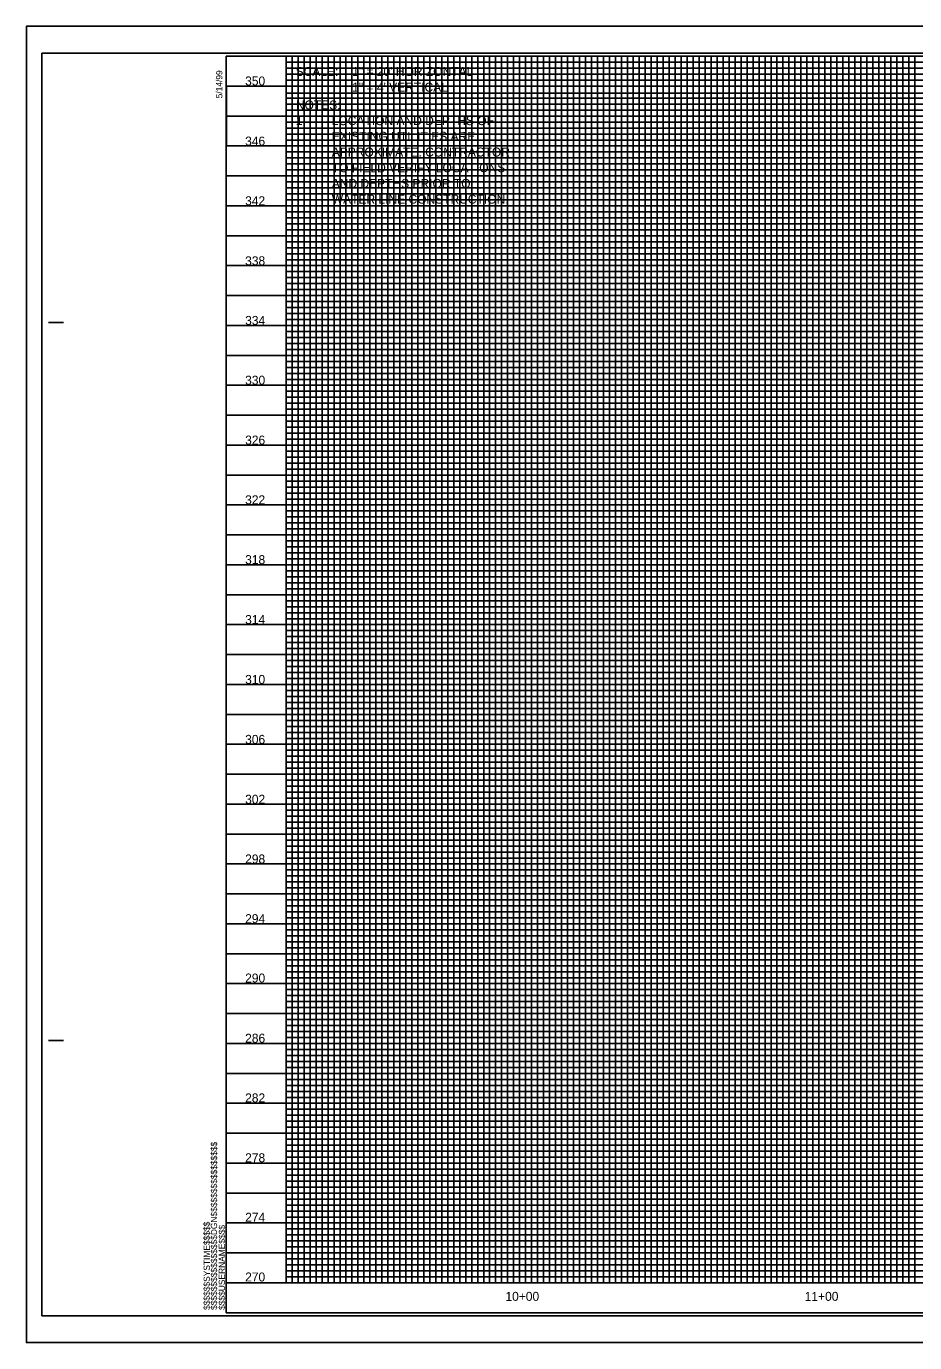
# Model space of a CAD drawing. Extents: x 3814791 to 3815465, y 1224203 to 1224643.
# Drawn here: x 3814791.3 to 3815088.1, y 1224203.2 to 1224643.2 of the extents above; entities that cross this region are included whole.
import ezdxf

# ---------------------------------------------------------------- set-up
doc = ezdxf.new("R2010")
doc.units = 0
for name, color, linetype in [('Exist Roads EOP', 7, 'Continuous'), ('General Text and Text Box and Leader Line', 7, 'Continuous'), ('Pattern 49', 7, 'Continuous'), ('Scratch_Level_1', 7, 'Continuous'), ('W 45 B (St) CELL', 7, 'Continuous'), ('Water Pump Station (St) CELL', 7, 'Continuous')]:
    doc.layers.add(name, color=color, linetype=linetype)

msp = doc.modelspace()

# ---------------------------------------------------------------- linework, layer by layer
at = {"layer": 'Exist Roads EOP'}
for p, q in [((3814878.11, 1224633.21), (3815378.11, 1224633.21)), ((3815438.11, 1224561.21), (3814878.11, 1224561.21)), ((3814878.11, 1224561.21), (3814878.11, 1224559.21)), ((3814878.11, 1224559.21), (3815438.11, 1224559.21)), ((3815438.11, 1224551.21), (3814878.11, 1224551.21)), ((3814798.71, 1224544.21), (3814803.71, 1224544.21)), ((3814798.71, 1224304.21), (3814803.71, 1224304.21)), ((3815458.11, 1224223.21), (3814858.11, 1224223.21)), ((3814878.11, 1224223.21), (3815438.11, 1224223.21)), ((3814858.11, 1224213.21), (3814858.11, 1224213.21)), ((3814858.11, 1224213.21), (3814858.11, 1224213.21)), ((3814858.11, 1224213.21), (3814858.11, 1224213.21)), ((3814858.11, 1224213.21), (3814858.11, 1224213.21)), ((3814858.11, 1224213.21), (3814858.11, 1224213.21)), ((3814858.11, 1224213.21), (3814858.11, 1224213.21))]:
    msp.add_line(p, q, dxfattribs=at)
for points in [[(3815458.11, 1224633.21), (3814858.11, 1224633.21), (3814858.11, 1224213.21), (3815458.11, 1224213.21)], [(3814878.11, 1224633.21), (3814878.11, 1224223.21), (3815438.11, 1224223.21), (3815438.11, 1224578.19), (3815378.11, 1224578.19), (3815378.11, 1224633.21)]]:
    msp.add_lwpolyline(points, close=True, dxfattribs=at)
for points in [[(3814878.11, 1224633.21), (3814878.11, 1224223.21), (3814898.11, 1224223.21), (3814898.11, 1224633.21), (3814918.11, 1224633.21), (3814918.11, 1224223.21), (3814938.11, 1224223.21), (3814938.11, 1224633.21), (3814958.11, 1224633.21), (3814958.11, 1224223.21), (3814978.11, 1224223.21), (3814978.11, 1224633.21), (3814998.11, 1224633.21), (3814998.11, 1224223.21), (3815018.11, 1224223.21), (3815018.11, 1224633.21), (3815038.11, 1224633.21), (3815038.11, 1224223.21), (3815058.11, 1224223.21), (3815058.11, 1224633.21), (3815078.11, 1224633.21), (3815078.11, 1224223.21), (3815098.11, 1224223.21)], [(3814878.11, 1224633.21), (3814880.11, 1224633.21), (3814880.11, 1224223.21), (3814882.11, 1224223.21), (3814882.11, 1224633.21), (3814884.11, 1224633.21), (3814884.11, 1224223.21), (3814886.11, 1224223.21), (3814886.11, 1224633.21), (3814890.11, 1224633.21), (3814890.11, 1224223.21), (3814892.11, 1224223.21), (3814892.11, 1224633.21), (3814894.11, 1224633.21), (3814894.11, 1224223.21), (3814896.11, 1224223.21), (3814896.11, 1224633.21), (3814900.11, 1224633.21), (3814900.11, 1224223.21), (3814902.11, 1224223.21), (3814902.11, 1224633.21), (3814904.11, 1224633.21), (3814904.11, 1224223.21), (3814906.11, 1224223.21), (3814906.11, 1224633.21), (3814910.11, 1224633.21), (3814910.11, 1224223.21), (3814912.11, 1224223.21), (3814912.11, 1224633.21), (3814914.11, 1224633.21), (3814914.11, 1224223.21), (3814916.11, 1224223.21), (3814916.11, 1224633.21), (3814920.11, 1224633.21), (3814920.11, 1224223.21), (3814922.11, 1224223.21), (3814922.11, 1224633.21), (3814924.11, 1224633.21), (3814924.11, 1224223.21), (3814926.11, 1224223.21), (3814926.11, 1224633.21), (3814930.11, 1224633.21), (3814930.11, 1224223.21), (3814932.11, 1224223.21), (3814932.11, 1224633.21), (3814934.11, 1224633.21), (3814934.11, 1224223.21), (3814936.11, 1224223.21), (3814936.11, 1224633.21), (3814940.11, 1224633.21), (3814940.11, 1224223.21), (3814942.11, 1224223.21), (3814942.11, 1224633.21), (3814944.11, 1224633.21), (3814944.11, 1224223.21)], [(3815378.09, 1224631.21), (3814878.11, 1224631.21), (3814878.11, 1224629.21), (3815378.09, 1224629.21)], [(3814888.11, 1224223.21), (3814888.11, 1224633.21), (3814908.11, 1224633.21), (3814908.11, 1224223.21), (3814928.11, 1224223.21), (3814928.11, 1224633.21), (3814948.11, 1224633.21), (3814948.11, 1224223.21), (3814968.11, 1224223.21), (3814968.11, 1224633.21), (3814988.11, 1224633.21), (3814988.11, 1224223.21), (3815008.11, 1224223.21), (3815008.11, 1224633.21), (3815028.11, 1224633.21), (3815028.11, 1224223.21), (3815048.11, 1224223.21), (3815048.11, 1224633.21), (3815068.11, 1224633.21), (3815068.11, 1224223.21), (3815088.11, 1224223.21), (3815088.11, 1224633.21)], [(3814944.11, 1224223.21), (3814946.11, 1224223.21), (3814946.11, 1224633.21), (3814950.11, 1224633.21), (3814950.11, 1224223.21), (3814952.11, 1224223.21), (3814952.11, 1224633.21), (3814954.11, 1224633.21), (3814954.11, 1224223.21), (3814956.11, 1224223.21), (3814956.11, 1224633.21), (3814960.11, 1224633.21), (3814960.11, 1224223.21), (3814962.11, 1224223.21), (3814962.11, 1224633.21), (3814962.11, 1224633.21), (3814964.11, 1224633.21), (3814964.11, 1224223.21), (3814966.11, 1224223.21), (3814966.11, 1224633.21), (3814970.11, 1224633.21), (3814970.11, 1224223.21), (3814972.11, 1224223.21), (3814972.11, 1224633.21), (3814974.11, 1224633.21), (3814974.11, 1224223.21), (3814976.11, 1224223.21), (3814976.11, 1224633.21), (3814980.11, 1224633.21), (3814980.11, 1224223.21), (3814982.11, 1224223.21), (3814982.11, 1224633.21), (3814984.11, 1224633.21), (3814984.11, 1224223.21), (3814986.11, 1224223.21), (3814986.11, 1224633.21), (3814990.11, 1224633.21), (3814990.11, 1224223.21), (3814992.11, 1224223.21), (3814992.11, 1224633.21), (3814994.11, 1224633.21), (3814994.11, 1224223.21), (3814996.11, 1224223.21), (3814996.11, 1224633.21), (3815000.11, 1224633.21), (3815000.11, 1224223.21), (3815002.11, 1224223.21), (3815002.11, 1224633.21), (3815004.11, 1224633.21), (3815004.11, 1224223.21), (3815006.11, 1224223.21), (3815006.11, 1224633.21), (3815010.11, 1224633.21), (3815010.11, 1224223.21), (3815016.11, 1224223.21), (3815016.11, 1224633.21), (3815020.11, 1224633.21), (3815020.11, 1224223.21), (3815022.11, 1224223.21), (3815022.11, 1224633.21), (3815024.11, 1224633.21), (3815024.11, 1224223.21), (3815026.11, 1224223.21), (3815026.11, 1224633.21), (3815030.11, 1224633.21), (3815030.11, 1224223.21), (3815032.11, 1224223.21), (3815032.11, 1224633.21), (3815034.11, 1224633.21), (3815034.11, 1224223.21), (3815036.11, 1224223.21), (3815036.11, 1224633.21), (3815040.11, 1224633.21), (3815040.11, 1224223.21), (3815042.11, 1224223.21), (3815042.11, 1224633.21), (3815044.11, 1224633.21), (3815044.11, 1224223.21), (3815046.11, 1224223.21), (3815046.11, 1224633.21), (3815050.11, 1224633.21), (3815050.11, 1224223.21), (3815052.11, 1224223.21), (3815052.11, 1224633.21), (3815054.11, 1224633.21), (3815054.11, 1224223.21), (3815056.11, 1224223.21), (3815056.11, 1224633.21), (3815060.11, 1224633.21), (3815060.11, 1224223.21), (3815062.11, 1224223.21), (3815062.11, 1224633.21), (3815064.11, 1224633.21), (3815064.11, 1224223.21), (3815066.11, 1224223.21), (3815066.11, 1224633.21), (3815070.11, 1224633.21), (3815070.11, 1224223.21)], [(3815012.11, 1224633.21), (3815012.11, 1224223.21), (3815014.11, 1224223.21), (3815014.11, 1224633.21)], [(3815012.11, 1224632.97), (3815012.11, 1224223.21), (3815014.11, 1224223.21), (3815014.11, 1224632.97)], [(3815072.11, 1224633.21), (3815072.11, 1224223.21), (3815074.11, 1224223.21), (3815074.11, 1224633.21), (3815076.11, 1224633.21), (3815076.11, 1224223.21), (3815080.11, 1224223.21), (3815080.11, 1224633.21), (3815082.11, 1224633.21), (3815082.11, 1224223.21), (3815084.11, 1224223.21), (3815084.11, 1224633.21), (3815086.11, 1224633.21), (3815086.11, 1224223.21)], [(3815378.09, 1224627.21), (3814878.11, 1224627.21), (3814878.11, 1224625.21), (3815378.09, 1224625.21)], [(3815378.09, 1224603.21), (3814858.15, 1224603.21), (3814858.15, 1224623.19), (3815378.09, 1224623.19)], [(3815378.09, 1224620.91), (3814878.11, 1224620.91), (3814878.11, 1224619.21), (3815378.09, 1224619.21)], [(3815378.09, 1224617.21), (3814878.11, 1224617.21), (3814878.11, 1224615.21), (3815378.09, 1224615.21)], [(3814858.11, 1224613.21), (3815378.09, 1224613.21)], [(3815378.09, 1224611.21), (3814878.11, 1224611.21), (3814878.11, 1224609.21), (3815378.09, 1224609.21)], [(3815378.11, 1224607.21), (3814878.11, 1224607.21), (3814878.11, 1224605.21), (3815378.09, 1224605.21)], [(3815378.09, 1224601.21), (3814878.11, 1224601.21), (3814878.11, 1224599.21), (3815378.09, 1224599.21)], [(3815378.09, 1224597.21), (3814878.11, 1224597.21), (3814878.11, 1224595.21), (3815378.09, 1224595.21)], [(3815378.09, 1224593.21), (3814858.11, 1224593.21), (3814858.11, 1224573.19), (3815458.11, 1224573.19)], [(3815378.09, 1224591.21), (3814878.11, 1224591.21), (3814878.11, 1224589.21), (3815378.09, 1224589.21)], [(3815378.09, 1224587.21), (3814878.11, 1224587.21), (3814878.11, 1224585.21), (3815378.09, 1224585.21)], [(3815458.11, 1224563.21), (3814858.11, 1224563.21), (3814858.11, 1224583.21), (3815378.09, 1224583.21)], [(3815378.09, 1224581.21), (3814878.11, 1224581.21), (3814878.11, 1224579.21), (3815378.09, 1224579.21)], [(3815438.11, 1224577.21), (3814878.11, 1224577.21), (3814878.11, 1224577.21), (3814878.11, 1224569.21), (3815458.11, 1224569.21)], [(3814878.11, 1224575.21), (3815378.11, 1224575.21)], [(3815438.11, 1224571.21), (3814878.11, 1224571.21)], [(3815438.11, 1224567.21), (3814878.11, 1224567.21), (3814878.11, 1224565.21), (3815438.11, 1224565.21)], [(3815438.11, 1224557.21), (3814878.11, 1224557.21), (3814878.11, 1224555.21), (3815438.11, 1224555.21)], [(3815458.11, 1224553.21), (3814858.11, 1224553.21), (3814858.11, 1224533.21), (3815458.11, 1224533.21)], [(3815438.11, 1224549.21), (3814878.11, 1224549.21), (3814878.11, 1224547.21), (3815438.11, 1224547.21)], [(3815458.11, 1224523.21), (3814858.11, 1224523.21), (3814858.11, 1224543.21), (3815458.11, 1224543.21)], [(3815438.11, 1224545.21), (3814878.11, 1224545.21)], [(3814878.11, 1224541.21), (3815438.11, 1224541.21)], [(3815438.11, 1224539.21), (3814878.11, 1224539.21), (3814878.11, 1224537.21), (3815438.11, 1224537.21)], [(3815438.11, 1224535.21), (3814878.11, 1224535.21), (3814878.11, 1224531.21), (3815438.11, 1224531.21)], [(3815438.11, 1224529.21), (3814878.11, 1224529.21), (3814878.11, 1224527.21), (3815438.11, 1224527.21)], [(3815438.11, 1224525.21), (3814878.11, 1224525.21), (3814878.11, 1224521.21), (3815438.11, 1224521.21)], [(3815438.11, 1224519.21), (3814878.11, 1224519.21), (3814878.11, 1224517.21), (3815438.11, 1224517.21)], [(3815458.11, 1224513.21), (3814858.11, 1224513.21), (3814858.11, 1224493.21), (3815458.11, 1224493.21)], [(3815438.11, 1224515.21), (3814878.11, 1224515.21), (3814878.11, 1224511.21), (3815438.11, 1224511.21)], [(3815438.11, 1224509.21), (3814878.11, 1224509.21), (3814878.11, 1224507.21), (3815438.11, 1224507.21)], [(3815458.11, 1224483.21), (3814858.11, 1224483.21), (3814858.11, 1224503.21), (3815458.11, 1224503.21)], [(3815438.11, 1224505.21), (3814878.11, 1224505.21), (3814878.11, 1224501.21), (3815438.11, 1224501.21)], [(3815438.11, 1224499.21), (3814878.11, 1224499.21), (3814878.11, 1224497.21), (3815438.11, 1224497.21)], [(3815438.11, 1224495.21), (3814878.11, 1224495.21), (3814878.11, 1224491.21), (3815438.11, 1224491.21)], [(3815438.11, 1224489.21), (3814878.11, 1224489.21), (3814878.11, 1224487.21), (3815438.11, 1224487.21)], [(3815438.11, 1224485.21), (3814878.11, 1224485.21), (3814878.11, 1224481.21), (3815438.11, 1224481.21)], [(3815438.11, 1224479.21), (3814878.11, 1224479.21), (3814878.11, 1224477.21), (3815438.11, 1224477.21)], [(3815458.11, 1224473.21), (3814858.11, 1224473.21), (3814858.11, 1224453.21), (3815458.11, 1224453.21)], [(3815438.11, 1224475.21), (3814878.11, 1224475.21), (3814878.11, 1224471.21), (3815438.11, 1224471.21)], [(3815438.11, 1224469.21), (3814878.11, 1224469.21), (3814878.11, 1224467.21), (3815438.11, 1224467.21)], [(3815458.11, 1224443.21), (3814858.11, 1224443.21), (3814858.11, 1224463.21), (3815458.11, 1224463.21)], [(3815438.11, 1224465.21), (3814878.11, 1224465.21), (3814878.11, 1224461.21), (3815438.11, 1224461.21)], [(3815438.11, 1224459.21), (3814878.11, 1224459.21), (3814878.11, 1224457.21), (3815438.11, 1224457.21)], [(3815438.11, 1224455.21), (3814878.11, 1224455.21), (3814878.11, 1224451.21), (3815438.11, 1224451.21)], [(3815438.11, 1224449.21), (3814878.11, 1224449.21), (3814878.11, 1224447.21), (3815438.11, 1224447.21)], [(3815438.11, 1224445.21), (3814878.11, 1224445.21), (3814878.11, 1224441.21), (3815438.11, 1224441.21)], [(3815438.11, 1224439.21), (3814878.11, 1224439.21), (3814878.11, 1224437.21), (3815438.11, 1224437.21)], [(3815458.11, 1224433.21), (3814858.11, 1224433.21), (3814858.11, 1224413.21), (3815458.11, 1224413.21)], [(3815438.11, 1224435.21), (3814878.11, 1224435.21), (3814878.11, 1224431.21), (3815438.11, 1224431.21)], [(3815438.11, 1224429.21), (3814878.11, 1224429.21), (3814878.11, 1224427.21), (3815438.11, 1224427.21)], [(3815458.11, 1224403.21), (3814858.11, 1224403.21), (3814858.11, 1224423.21), (3815458.11, 1224423.21)], [(3815438.11, 1224425.21), (3814878.11, 1224425.21)], [(3814878.11, 1224421.21), (3815438.11, 1224421.21)], [(3815438.11, 1224419.21), (3814878.11, 1224419.21), (3814878.11, 1224417.21), (3815438.11, 1224417.21)], [(3815438.11, 1224415.21), (3814878.11, 1224415.21), (3814878.11, 1224411.21), (3815438.11, 1224411.21)], [(3815438.11, 1224409.21), (3814878.11, 1224409.21), (3814878.11, 1224407.21), (3815438.11, 1224407.21)], [(3815438.11, 1224405.21), (3814878.11, 1224405.21), (3814878.11, 1224401.21), (3815438.11, 1224401.21)], [(3815438.11, 1224399.21), (3814878.11, 1224399.21), (3814878.11, 1224397.21), (3815438.11, 1224397.21)], [(3815458.11, 1224393.21), (3814858.11, 1224393.21), (3814858.11, 1224373.21), (3815458.11, 1224373.21)], [(3815438.11, 1224395.21), (3814878.11, 1224395.21), (3814878.11, 1224391.21), (3815438.11, 1224391.21)], [(3815438.11, 1224389.21), (3814878.11, 1224389.21), (3814878.11, 1224387.21), (3815438.11, 1224387.21)], [(3815438.11, 1224385.21), (3814878.11, 1224385.21), (3814878.11, 1224381.21), (3815438.11, 1224381.21)], [(3815458.11, 1224363.21), (3814858.11, 1224363.21), (3814858.11, 1224383.21), (3815458.11, 1224383.21)], [(3815438.11, 1224379.21), (3814878.11, 1224379.21), (3814878.11, 1224377.21), (3815438.11, 1224377.21)], [(3815438.11, 1224375.21), (3814878.11, 1224375.21), (3814878.11, 1224371.21), (3815438.11, 1224371.21)], [(3815438.11, 1224369.21), (3814878.11, 1224369.21), (3814878.11, 1224367.21), (3815438.11, 1224367.21)], [(3815438.11, 1224365.21), (3814878.11, 1224365.21), (3814878.11, 1224361.21), (3815438.11, 1224361.21)], [(3815438.11, 1224359.21), (3814878.11, 1224359.21), (3814878.11, 1224357.21), (3815438.11, 1224357.21)], [(3815458.11, 1224353.21), (3814858.11, 1224353.21), (3814858.11, 1224333.21), (3815458.11, 1224333.21)], [(3815438.11, 1224355.21), (3814878.11, 1224355.21), (3814878.11, 1224351.21), (3815438.11, 1224351.21)], [(3815438.11, 1224349.21), (3814878.11, 1224349.21), (3814878.11, 1224347.21), (3815438.11, 1224347.21)], [(3815438.11, 1224345.21), (3814878.11, 1224345.21), (3814878.11, 1224341.21), (3815438.11, 1224341.21)], [(3815458.11, 1224323.21), (3814858.11, 1224323.21), (3814858.11, 1224343.21), (3815458.11, 1224343.21)], [(3815438.11, 1224339.21), (3814878.11, 1224339.21), (3814878.11, 1224337.21), (3815438.11, 1224337.21)], [(3815438.11, 1224335.21), (3814878.11, 1224335.21), (3814878.11, 1224331.21), (3815438.11, 1224331.21)], [(3815438.11, 1224329.21), (3814878.11, 1224329.21), (3814878.11, 1224327.21), (3815438.11, 1224327.21)], [(3815438.11, 1224325.21), (3814878.11, 1224325.21), (3814878.11, 1224321.21), (3815438.11, 1224321.21)], [(3815438.11, 1224319.21), (3814878.11, 1224319.21), (3814878.11, 1224317.21), (3815438.11, 1224317.21)], [(3815458.11, 1224313.21), (3814858.11, 1224313.21), (3814858.11, 1224293.21), (3815458.11, 1224293.21)], [(3815438.11, 1224315.21), (3814878.11, 1224315.21), (3814878.11, 1224311.21), (3815438.11, 1224311.21)], [(3815438.11, 1224309.21), (3814878.11, 1224309.21), (3814878.11, 1224307.21), (3815438.11, 1224307.21)], [(3815438.11, 1224305.21), (3814878.11, 1224305.21)], [(3815458.11, 1224283.21), (3814858.11, 1224283.21), (3814858.11, 1224303.21), (3815458.11, 1224303.21)], [(3814878.11, 1224301.21), (3815438.11, 1224301.21)], [(3815438.11, 1224299.21), (3814878.11, 1224299.21), (3814878.11, 1224297.21), (3815438.11, 1224297.21)], [(3815438.11, 1224295.21), (3814878.11, 1224295.21)], [(3814878.11, 1224291.21), (3815438.11, 1224291.21)], [(3815438.11, 1224289.21), (3814878.11, 1224289.21), (3814878.11, 1224287.21), (3815438.11, 1224287.21)], [(3815438.11, 1224285.21), (3814878.11, 1224285.21), (3814878.11, 1224281.21), (3815438.11, 1224281.21)], [(3815438.11, 1224279.21), (3814878.11, 1224279.21), (3814878.11, 1224277.21), (3815438.11, 1224277.21)], [(3815438.11, 1224275.21), (3814878.11, 1224275.21), (3814878.11, 1224271.21), (3815438.11, 1224271.21)], [(3815458.11, 1224273.21), (3814858.11, 1224273.21), (3814858.11, 1224253.21), (3815458.11, 1224253.21)], [(3815438.11, 1224269.21), (3814878.11, 1224269.21), (3814878.11, 1224267.21), (3815438.11, 1224267.21)], [(3815438.11, 1224265.21), (3814878.11, 1224265.21), (3814878.11, 1224261.21), (3815438.11, 1224261.21)], [(3815458.11, 1224243.21), (3814858.11, 1224243.21), (3814858.11, 1224263.21), (3815458.11, 1224263.21)], [(3815438.11, 1224259.21), (3814878.11, 1224259.21), (3814878.11, 1224257.21), (3815438.11, 1224257.21)], [(3815438.11, 1224255.21), (3814878.11, 1224255.21), (3814878.11, 1224251.21), (3815438.11, 1224251.21)], [(3815438.11, 1224249.21), (3814878.11, 1224249.21), (3814878.11, 1224247.21), (3815438.11, 1224247.21)], [(3815438.11, 1224245.21), (3814878.11, 1224245.21), (3814878.11, 1224241.21), (3815438.11, 1224241.21)], [(3815438.11, 1224239.21), (3814878.11, 1224239.21), (3814878.11, 1224237.21), (3815438.11, 1224237.21)], [(3815438.11, 1224235.21), (3814878.11, 1224235.21), (3814878.11, 1224231.21), (3815438.11, 1224231.21)], [(3815458.11, 1224233.21), (3814858.11, 1224233.21)], [(3815438.11, 1224229.21), (3814878.11, 1224229.21), (3814878.11, 1224227.21), (3815438.11, 1224227.21)], [(3815438.11, 1224225.21), (3814878.11, 1224225.21)], [(3814873.11, 1224213.21), (3814873.11, 1224213.21)]]:
    msp.add_lwpolyline(points, dxfattribs=at)
at = {"layer": 'Pattern 49'}
msp.add_lwpolyline([(3815463.11, 1224634.23), (3814796.51, 1224634.23), (3814796.51, 1224212.19), (3815463.11, 1224212.19)], close=True, dxfattribs=at)
at = {"layer": 'Scratch_Level_1'}
msp.add_lwpolyline([(3815464.91, 1224643.21), (3814791.31, 1224643.21), (3814791.31, 1224203.21), (3815464.91, 1224203.21)], close=True, dxfattribs=at)

# ---------------------------------------------------------------- texts
at = {"layer": 'Exist Roads EOP'}
for s, p in [('5/14/99', (3814856.81, 1224619.13)), ('$$$$$$$$$$$$$$$$DGN$$$$$$$$$$$$$$$$', (3814855.05, 1224214.15)), ('$$$$$$SYSTIME$$$$$', (3814852.63, 1224214.15)), ('$$$$USERNAME$$$$', (3814857.68, 1224214.16))]:
    msp.add_text(s, height=2.1, rotation=90, dxfattribs=at).set_placement(p)
at = {"layer": 'General Text and Text Box and Leader Line'}
for s, p in [('350', (3814864.41, 1224623.44)), ('346', (3814864.41, 1224603.34)), ('342', (3814864.41, 1224583.4)), ('338', (3814864.41, 1224563.33)), ('334', (3814864.41, 1224543.4)), ('330', (3814864.41, 1224523.43)), ('326', (3814864.41, 1224503.4)), ('322', (3814864.41, 1224483.44)), ('318', (3814864.41, 1224463.44)), ('314', (3814864.41, 1224443.43)), ('310', (3814864.41, 1224423.4)), ('306', (3814864.41, 1224403.36)), ('302', (3814864.41, 1224383.34)), ('298', (3814864.41, 1224363.39)), ('294', (3814864.41, 1224343.43)), ('290', (3814864.41, 1224323.59)), ('286', (3814864.41, 1224303.48)), ('282', (3814864.41, 1224283.52)), ('278', (3814864.41, 1224263.52)), ('274', (3814864.41, 1224243.62)), ('270', (3814864.41, 1224223.66))]:
    msp.add_text(s, height=3, dxfattribs=at).set_placement(p)
at = {"layer": 'W 45 B (St) CELL'}
for s, p in [('SCALE: ', (3814881.28, 1224626.62)), ('1" = 20\' HORIZONTAL', (3814900.19, 1224626.62)), ('1" = 4\' VERTICAL', (3814900.19, 1224621.37)), ('NOTES:', (3814881.36, 1224615.43)), ('1.', (3814881.36, 1224610.18)), ('LOCATION AND DEPTHS OF', (3814893.36, 1224610.18)), ('EXISTING UTILITIES ARE', (3814893.36, 1224604.94)), ('APPROXIMATE. CONTRACTOR', (3814893.36, 1224599.69)), ('TO FIELD VERIFY LOCATIONS', (3814893.36, 1224594.44)), ('AND DEPTHS PRIOR TO', (3814893.36, 1224589.19)), ('WATER LINE CONSTRUCTION.', (3814893.36, 1224583.94))]:
    msp.add_text(s, height=3, dxfattribs=at).set_placement(p)
at = {"layer": 'Water Pump Station (St) CELL'}
for s, p in [('10+00', (3814951.38, 1224217.19)), ('11+00', (3815051.37, 1224217.19))]:
    msp.add_text(s, height=3, dxfattribs=at).set_placement(p)

doc.saveas('drawing.dxf')
